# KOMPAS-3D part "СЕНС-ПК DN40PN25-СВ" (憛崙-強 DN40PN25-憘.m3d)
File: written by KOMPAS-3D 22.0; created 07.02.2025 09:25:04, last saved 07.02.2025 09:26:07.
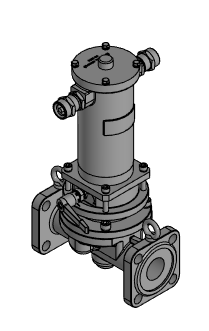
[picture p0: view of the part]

Document properties: Автор: setup; Полное имя файла: \\10.10.77.77\!! users\Савин А.Г\!Клапаны 3D для заказчика\СЕНС-ПК\1. СЕНС-ПК\СЕНС-ПК DN40PN25-СВ.m3d

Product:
- Body: Тело 3
    Масса: 16.691352
- Part/product: СЕНС-ПК DN40PN25-СВ
    Масса: 16.470884

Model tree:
1. Операция без истории:1  (labels: ␣?ā0)
2. Эскиз:1  (with: Операция без истории:1)
3. Элемент выдавливания:1
     Расстояние 1 = 14
4. Фаска:1  (with: Элемент выдавливания:1)
     Угол = 45; Длина 1 = 2; Длина 2 = 2

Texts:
  Body Specification ( left align )
  Body Specificaton ( centered )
